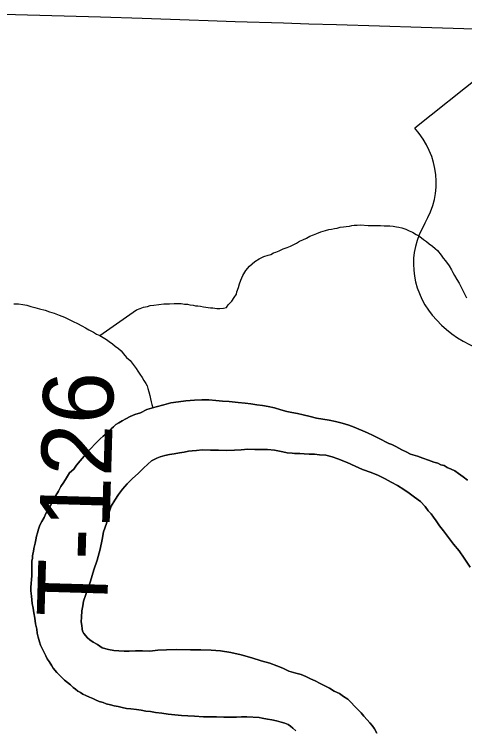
# Model space of a CAD drawing. Extents: x 2.1 to 73.9, y 4 to 26.
# Drawn here: x 43.881 to 44.0631, y 22.0785 to 22.368 of the extents above; entities that cross this region are included whole.
import ezdxf

# ---------------------------------------------------------------- set-up
doc = ezdxf.new("R2010")
doc.units = 0
for name, color, linetype in [('GM_X_County_Road', 7, 'Continuous'), ('GM_X_Major_River', 7, 'Continuous'), ('GM_X_Minor_River', 7, 'Continuous'), ('GM_X_Township_Road_Text', 7, 'Continuous'), ('GM_X_US_Shield', 7, 'Continuous')]:
    doc.layers.add(name, color=color, linetype=linetype)

msp = doc.modelspace()

# ---------------------------------------------------------------- linework, layer by layer
at = {"layer": 'GM_X_County_Road'}
msp.add_lwpolyline([(43.87654, 22.368), (43.89134, 22.36761), (43.91589, 22.36695), (43.93267, 22.36645), (43.95162, 22.36577), (43.95938, 22.36552), (43.97026, 22.36514), (43.98982, 22.3645), (44.00007, 22.36416), (44.01125, 22.36384), (44.02865, 22.36335), (44.04542, 22.36273), (44.06698, 22.36211), (44.08797, 22.36138), (44.10382, 22.36093), (44.1234, 22.36019), (44.12722, 22.36005)], dxfattribs=at)
at = {"layer": 'GM_X_Major_River'}
for points in [[(44.02771, 22.19681), (44.02601, 22.1976), (44.02374, 22.19859), (44.01845, 22.20095), (44.01619, 22.20175), (44.01353, 22.20255), (44.01088, 22.20316), (44.00823, 22.20378), (44.00576, 22.2042), (44.00311, 22.20462), (44.00064, 22.20523), (43.9978, 22.20585), (43.99553, 22.20645), (43.99325, 22.20687), (43.99117, 22.20728), (43.98871, 22.20789), (43.98624, 22.2087), (43.98359, 22.20931), (43.98132, 22.20973), (43.97904, 22.20995), (43.97657, 22.21037), (43.97429, 22.2106), (43.97144, 22.21084), (43.96784, 22.21127), (43.96518, 22.21151), (43.96252, 22.21174), (43.95967, 22.21198), (43.95682, 22.21202), (43.95377, 22.21188), (43.95035, 22.21156), (43.9473, 22.21123), (43.94425, 22.21071), (43.94138, 22.20999), (43.93833, 22.20909), (43.9345, 22.20802), (43.93201, 22.20673), (43.92972, 22.206), (43.92781, 22.20528), (43.92608, 22.20435), (43.92454, 22.20343), (43.9232, 22.20269), (43.92205, 22.20195), (43.92108, 22.20102), (43.92012, 22.20027), (43.91915, 22.19934), (43.91819, 22.1984), (43.91684, 22.19728), (43.91568, 22.19616), (43.91452, 22.19504), (43.91336, 22.19392), (43.9122, 22.19261), (43.91104, 22.1913), (43.90988, 22.18999), (43.90619, 22.18549), (43.90503, 22.18399), (43.9033, 22.18249), (43.90212, 22.18042), (43.90095, 22.17873), (43.89978, 22.17685), (43.8988, 22.17497), (43.89783, 22.17327), (43.89704, 22.17176), (43.89626, 22.17045), (43.89548, 22.16894), (43.8945, 22.16744), (43.89372, 22.16593), (43.89312, 22.16442), (43.89214, 22.16272), (43.89136, 22.16122), (43.89077, 22.15971), (43.89036, 22.15819), (43.88996, 22.15687), (43.88975, 22.15535), (43.88935, 22.15403), (43.88914, 22.15289), (43.88893, 22.15176), (43.88872, 22.15062), (43.88852, 22.14967), (43.88831, 22.14873), (43.8883, 22.14778), (43.88809, 22.14683), (43.88808, 22.14588), (43.88806, 22.14493), (43.88804, 22.14379), (43.88802, 22.14227), (43.888, 22.14075), (43.88797, 22.13923), (43.88776, 22.13771), (43.88773, 22.1362), (43.88771, 22.13468), (43.88787, 22.13258), (43.88803, 22.13106), (43.8882, 22.12954), (43.88855, 22.12763), (43.8889, 22.12573), (43.88925, 22.12363), (43.88959, 22.12134), (43.89013, 22.11925), (43.89029, 22.11753), (43.89065, 22.11601), (43.89119, 22.1141)], [(43.89119, 22.1141), (43.89065, 22.11601), (43.89029, 22.11753), (43.89013, 22.11925), (43.88959, 22.12134), (43.88925, 22.12363), (43.8889, 22.12573), (43.88855, 22.12763), (43.8882, 22.12954), (43.88803, 22.13106), (43.88787, 22.13258), (43.88771, 22.13468), (43.88773, 22.1362), (43.88776, 22.13771), (43.88797, 22.13923), (43.888, 22.14075), (43.88802, 22.14227), (43.88804, 22.14379), (43.88806, 22.14493), (43.88808, 22.14588), (43.88809, 22.14683), (43.8883, 22.14778), (43.88831, 22.14873), (43.88852, 22.14967), (43.88872, 22.15062), (43.88893, 22.15176), (43.88914, 22.15289), (43.88935, 22.15403), (43.88975, 22.15535), (43.88996, 22.15687), (43.89036, 22.15819), (43.89077, 22.15971), (43.89136, 22.16122), (43.89214, 22.16272), (43.89312, 22.16442), (43.89372, 22.16593), (43.8945, 22.16744), (43.89548, 22.16894), (43.89626, 22.17045), (43.89704, 22.17176), (43.89783, 22.17327), (43.8988, 22.17497), (43.89978, 22.17685), (43.90095, 22.17873), (43.90212, 22.18042), (43.9033, 22.18249), (43.90503, 22.18399), (43.90619, 22.18549), (43.90988, 22.18999), (43.91104, 22.1913), (43.9122, 22.19261), (43.91336, 22.19392), (43.91452, 22.19504), (43.91568, 22.19616), (43.91684, 22.19728), (43.91819, 22.1984), (43.91915, 22.19934), (43.92012, 22.20027), (43.92108, 22.20102), (43.92205, 22.20195), (43.9232, 22.20269), (43.92454, 22.20343), (43.92608, 22.20435), (43.92781, 22.20528), (43.92972, 22.206), (43.93201, 22.20673), (43.9345, 22.20802), (43.93833, 22.20909), (43.94138, 22.20999), (43.94425, 22.21071), (43.9473, 22.21123), (43.95035, 22.21156), (43.95377, 22.21188), (43.95682, 22.21202), (43.95967, 22.21198), (43.96252, 22.21174), (43.96518, 22.21151), (43.96784, 22.21127), (43.97144, 22.21084), (43.97429, 22.2106), (43.97657, 22.21037), (43.97904, 22.20995), (43.98132, 22.20973), (43.98359, 22.20931), (43.98624, 22.2087), (43.98871, 22.20789), (43.99117, 22.20728), (43.99325, 22.20687), (43.99553, 22.20645), (43.9978, 22.20585), (44.00064, 22.20523), (44.00311, 22.20462), (44.00576, 22.2042), (44.00823, 22.20378), (44.01088, 22.20316), (44.01353, 22.20255), (44.01619, 22.20175), (44.01845, 22.20095), (44.02374, 22.19859), (44.02601, 22.1976), (44.02771, 22.19681)], [(44.06414, 22.1795), (44.06245, 22.18086), (44.06057, 22.18222), (44.05907, 22.18319), (44.05756, 22.18398), (44.05604, 22.18457), (44.05472, 22.18535), (44.0534, 22.18575), (44.05227, 22.18634), (44.05056, 22.18675), (44.04848, 22.18754), (44.04621, 22.18834), (44.04394, 22.18914), (44.0411, 22.18995), (44.03941, 22.19092), (44.03771, 22.19171), (44.03526, 22.19308), (44.03356, 22.19387), (44.03242, 22.19427), (44.0311, 22.19505), (44.02959, 22.19583), (44.02771, 22.19681)], [(44.02771, 22.19681), (44.02959, 22.19583), (44.0311, 22.19505), (44.03242, 22.19427), (44.03356, 22.19387), (44.03526, 22.19308), (44.03771, 22.19171), (44.03941, 22.19092), (44.0411, 22.18995), (44.04394, 22.18914), (44.04621, 22.18834), (44.04848, 22.18754), (44.05056, 22.18675), (44.05227, 22.18634), (44.0534, 22.18575), (44.05472, 22.18535), (44.05604, 22.18457), (44.05756, 22.18398), (44.05907, 22.18319), (44.06057, 22.18222), (44.06245, 22.18086), (44.06414, 22.1795)], [(44.02754, 22.07711), (44.02662, 22.07883), (44.02569, 22.08018), (44.02476, 22.08133), (44.02363, 22.08249), (44.02233, 22.08403), (44.02121, 22.08538), (44.0199, 22.08673), (44.01578, 22.09079), (44.01408, 22.09196), (44.01239, 22.09312), (44.01031, 22.09411), (44.00843, 22.09528), (44.00654, 22.09626), (44.00466, 22.09724), (44.00258, 22.09822), (44.00069, 22.09902), (43.9988, 22.1), (43.99691, 22.10079), (43.99483, 22.10139), (43.99199, 22.1022), (43.98954, 22.10338), (43.98708, 22.10437), (43.98424, 22.10536), (43.98084, 22.10637), (43.97705, 22.10757), (43.9727, 22.10878), (43.96853, 22.1098), (43.96435, 22.11044), (43.96055, 22.11069), (43.95637, 22.11076), (43.95219, 22.11082), (43.94648, 22.11092), (43.94249, 22.11079), (43.93906, 22.11066), (43.93582, 22.11033), (43.93278, 22.11038), (43.92993, 22.11043), (43.92746, 22.11028), (43.92537, 22.11031), (43.92327, 22.11035), (43.92118, 22.11057), (43.9191, 22.11098), (43.91645, 22.1116), (43.91457, 22.11296), (43.91287, 22.11393), (43.91155, 22.11491), (43.91061, 22.11568), (43.90912, 22.11742), (43.90857, 22.11837), (43.90839, 22.11933), (43.90822, 22.12066), (43.90805, 22.12218), (43.90808, 22.12408), (43.90831, 22.12655), (43.90873, 22.12863), (43.90895, 22.13053), (43.91174, 22.13865), (43.91314, 22.14319), (43.91453, 22.14716), (43.91574, 22.15151), (43.91656, 22.15549), (43.91699, 22.15852), (43.91819, 22.16192), (43.9192, 22.16608), (43.9202, 22.16892), (43.92157, 22.17137), (43.92312, 22.17362), (43.92468, 22.17587), (43.92662, 22.17793), (43.92874, 22.18018), (43.93106, 22.18223), (43.93318, 22.18429), (43.93492, 22.18597), (43.93646, 22.18727), (43.93857, 22.18838), (43.93991, 22.18893), (43.94182, 22.18947), (43.94373, 22.18982), (43.94564, 22.19016), (43.94773, 22.19051), (43.94964, 22.19086), (43.95136, 22.19121), (43.95288, 22.19138), (43.9546, 22.19154), (43.95688, 22.19169), (43.9603, 22.19164), (43.96353, 22.19158), (43.96696, 22.19153), (43.97, 22.19167), (43.97267, 22.19182), (43.97533, 22.19196), (43.97818, 22.19191)], [(43.97818, 22.19191), (43.97533, 22.19196), (43.97267, 22.19182), (43.97, 22.19167), (43.96696, 22.19153), (43.96353, 22.19158), (43.9603, 22.19164), (43.95688, 22.19169), (43.9546, 22.19154), (43.95288, 22.19138), (43.95136, 22.19121), (43.94964, 22.19086), (43.94773, 22.19051), (43.94564, 22.19016), (43.94373, 22.18982), (43.94182, 22.18947), (43.93991, 22.18893), (43.93857, 22.18838), (43.93646, 22.18727), (43.93492, 22.18597), (43.93318, 22.18429), (43.93106, 22.18223), (43.92874, 22.18018), (43.92662, 22.17793), (43.92468, 22.17587), (43.92312, 22.17362), (43.92157, 22.17137), (43.9202, 22.16892), (43.9192, 22.16608), (43.91819, 22.16192), (43.91699, 22.15852), (43.91656, 22.15549), (43.91574, 22.15151), (43.91453, 22.14716), (43.91314, 22.14319), (43.91174, 22.13865), (43.90895, 22.13053), (43.90873, 22.12863), (43.90831, 22.12655), (43.90808, 22.12408), (43.90805, 22.12218), (43.90822, 22.12066), (43.90839, 22.11933), (43.90857, 22.11837), (43.90912, 22.11742), (43.91061, 22.11568), (43.91155, 22.11491), (43.91287, 22.11393), (43.91457, 22.11296), (43.91645, 22.1116), (43.9191, 22.11098), (43.92118, 22.11057), (43.92327, 22.11035), (43.92537, 22.11031), (43.92746, 22.11028), (43.92993, 22.11043), (43.93278, 22.11038), (43.93582, 22.11033), (43.93906, 22.11066), (43.94249, 22.11079), (43.94648, 22.11092), (43.95219, 22.11082), (43.95637, 22.11076), (43.96055, 22.11069), (43.96435, 22.11044), (43.96853, 22.1098), (43.9727, 22.10878), (43.97705, 22.10757), (43.98084, 22.10637), (43.98424, 22.10536), (43.98708, 22.10437), (43.98954, 22.10338), (43.99199, 22.1022), (43.99483, 22.10139), (43.99691, 22.10079), (43.9988, 22.1), (44.00069, 22.09902), (44.00258, 22.09822), (44.00466, 22.09724), (44.00654, 22.09626), (44.00843, 22.09528), (44.01031, 22.09411), (44.01239, 22.09312), (44.01408, 22.09196), (44.01578, 22.09079), (44.0199, 22.08673), (44.02121, 22.08538), (44.02233, 22.08403), (44.02363, 22.08249), (44.02476, 22.08133), (44.02569, 22.08018), (44.02662, 22.07883), (44.02754, 22.07711)], [(43.97818, 22.19191), (43.98085, 22.19187), (43.98332, 22.19183), (43.98617, 22.1916), (43.98958, 22.19097), (43.99129, 22.19056), (43.99337, 22.19034), (43.99432, 22.19032), (43.99528, 22.19031), (43.99642, 22.19029), (43.99812, 22.19007), (44.00022, 22.19004), (44.00231, 22.19), (44.0044, 22.18978), (44.00687, 22.18955), (44.00952, 22.18894), (44.01179, 22.18814), (44.01557, 22.18656), (44.01878, 22.18518), (44.0218, 22.1838), (44.0252, 22.1826), (44.02823, 22.18141), (44.03087, 22.18004), (44.03332, 22.17867), (44.03596, 22.1773), (44.03841, 22.17574), (44.04067, 22.17418), (44.04273, 22.17263), (44.04518, 22.17088), (44.04705, 22.16876), (44.04835, 22.16703), (44.04947, 22.16587), (44.0504, 22.16452), (44.05152, 22.16298), (44.05282, 22.16106), (44.0545, 22.15895), (44.05655, 22.15625), (44.0586, 22.15356), (44.06084, 22.15086), (44.06289, 22.14798), (44.0653, 22.14433)], [(44.0653, 22.14433), (44.06289, 22.14798), (44.06084, 22.15086), (44.0586, 22.15356), (44.05655, 22.15625), (44.0545, 22.15895), (44.05282, 22.16106), (44.05152, 22.16298), (44.0504, 22.16452), (44.04947, 22.16587), (44.04835, 22.16703), (44.04705, 22.16876), (44.04518, 22.17088), (44.04273, 22.17263), (44.04067, 22.17418), (44.03841, 22.17574), (44.03596, 22.1773), (44.03332, 22.17867), (44.03087, 22.18004), (44.02823, 22.18141), (44.0252, 22.1826), (44.0218, 22.1838), (44.01878, 22.18518), (44.01557, 22.18656), (44.01179, 22.18814), (44.00952, 22.18894), (44.00687, 22.18955), (44.0044, 22.18978), (44.00231, 22.19), (44.00022, 22.19004), (43.99812, 22.19007), (43.99642, 22.19029), (43.99528, 22.19031), (43.99432, 22.19032), (43.99337, 22.19034), (43.99129, 22.19056), (43.98958, 22.19097), (43.98617, 22.1916), (43.98332, 22.19183), (43.98085, 22.19187), (43.97818, 22.19191)], [(43.89119, 22.1141), (43.89155, 22.11276), (43.89376, 22.10836), (43.89432, 22.10721), (43.89506, 22.10605), (43.89617, 22.10433), (43.89673, 22.10337), (43.89822, 22.10163), (43.89935, 22.10047), (43.90028, 22.09951), (43.90122, 22.09854), (43.90253, 22.09757), (43.90366, 22.0966), (43.90478, 22.09564), (43.90572, 22.09486), (43.90666, 22.09408), (43.90779, 22.0935), (43.90874, 22.09291), (43.90987, 22.09232), (43.91138, 22.09173), (43.9127, 22.09114), (43.91383, 22.09055), (43.91535, 22.08995), (43.91686, 22.08955), (43.91818, 22.08896), (43.91989, 22.08855), (43.9214, 22.08814), (43.92292, 22.08793), (43.92463, 22.08752), (43.92633, 22.08711), (43.92804, 22.0869), (43.93032, 22.08667), (43.93222, 22.08645), (43.93411, 22.08604), (43.93601, 22.08582), (43.9381, 22.0854), (43.94057, 22.08517), (43.94322, 22.08475), (43.94588, 22.08452), (43.94854, 22.08428), (43.9512, 22.08405), (43.95386, 22.08401), (43.95747, 22.08376), (43.96013, 22.08371), (43.96279, 22.08367), (43.96565, 22.08362), (43.96831, 22.08358), (43.97078, 22.08354), (43.97287, 22.0837), (43.97496, 22.08366), (43.97991, 22.08339), (43.98123, 22.08318), (43.98332, 22.08277), (43.98503, 22.08255), (43.98692, 22.08214), (43.98882, 22.08154), (43.99033, 22.08113), (43.99165, 22.08054), (43.99259, 22.07996), (43.99353, 22.07918), (43.99485, 22.07802)], [(43.99485, 22.07802), (43.99353, 22.07918), (43.99259, 22.07996), (43.99165, 22.08054), (43.99033, 22.08113), (43.98882, 22.08154), (43.98692, 22.08214), (43.98503, 22.08255), (43.98332, 22.08277), (43.98123, 22.08318), (43.97991, 22.08339), (43.97496, 22.08366), (43.97287, 22.0837), (43.97078, 22.08354), (43.96831, 22.08358), (43.96565, 22.08362), (43.96279, 22.08367), (43.96013, 22.08371), (43.95747, 22.08376), (43.95386, 22.08401), (43.9512, 22.08405), (43.94854, 22.08428), (43.94588, 22.08452), (43.94322, 22.08475), (43.94057, 22.08517), (43.9381, 22.0854), (43.93601, 22.08582), (43.93411, 22.08604), (43.93222, 22.08645), (43.93032, 22.08667), (43.92804, 22.0869), (43.92633, 22.08711), (43.92463, 22.08752), (43.92292, 22.08793), (43.9214, 22.08814), (43.91989, 22.08855), (43.91818, 22.08896), (43.91686, 22.08955), (43.91535, 22.08995), (43.91383, 22.09055), (43.9127, 22.09114), (43.91138, 22.09173), (43.90987, 22.09232), (43.90874, 22.09291), (43.90779, 22.0935), (43.90666, 22.09408), (43.90572, 22.09486), (43.90478, 22.09564), (43.90366, 22.0966), (43.90253, 22.09757), (43.90122, 22.09854), (43.90028, 22.09951), (43.89935, 22.10047), (43.89822, 22.10163), (43.89673, 22.10337), (43.89617, 22.10433), (43.89506, 22.10605), (43.89432, 22.10721), (43.89376, 22.10836), (43.89155, 22.11276), (43.89119, 22.1141)]]:
    msp.add_lwpolyline(points, dxfattribs=at)
at = {"layer": 'GM_X_Minor_River'}
for points in [[(43.91558, 22.23796), (43.93038, 22.24836), (43.93191, 22.24891), (43.93325, 22.24946), (43.93478, 22.24981), (43.93593, 22.25018), (43.93745, 22.25034), (43.93935, 22.2505), (43.94145, 22.25085), (43.94373, 22.25081), (43.94564, 22.25097), (43.94716, 22.25094), (43.94849, 22.25092), (43.94982, 22.25071), (43.95096, 22.25069), (43.95191, 22.25048), (43.95324, 22.25027), (43.95418, 22.25007), (43.95513, 22.25005), (43.95627, 22.24984), (43.95741, 22.24964), (43.95836, 22.24943), (43.95931, 22.24941), (43.96026, 22.24921), (43.96121, 22.24919), (43.96291, 22.24898), (43.96406, 22.24896), (43.96558, 22.24912), (43.96672, 22.24929), (43.9675, 22.25042), (43.96886, 22.25192), (43.96983, 22.25342), (43.9708, 22.25474), (43.97101, 22.25568), (43.9716, 22.25739), (43.97201, 22.2589), (43.9726, 22.26041), (43.973, 22.26135), (43.97339, 22.2623), (43.97457, 22.26437), (43.97612, 22.26605), (43.97708, 22.26699), (43.97824, 22.26792), (43.97996, 22.26903), (43.98188, 22.26995), (43.9836, 22.27049), (43.98475, 22.27085), (43.98571, 22.27141), (43.98666, 22.27177), (43.988, 22.27232), (43.98973, 22.27305), (43.99126, 22.2736), (43.9926, 22.27415), (43.99394, 22.27488), (43.99509, 22.27543), (43.99624, 22.27618), (43.99758, 22.27673), (43.99912, 22.27746), (44.00046, 22.2782), (44.00199, 22.27874), (44.00333, 22.27929), (44.00486, 22.28003), (44.00677, 22.28057), (44.00811, 22.28092), (44.00925, 22.2811), (44.0104, 22.28127), (44.01154, 22.28144), (44.01269, 22.2818), (44.01402, 22.28197), (44.01516, 22.28214), (44.0165, 22.28231), (44.01745, 22.28248), (44.01841, 22.28266), (44.01955, 22.28264), (44.02088, 22.28281), (44.02411, 22.28257), (44.02506, 22.28255), (44.02601, 22.28253), (44.02715, 22.28252), (44.0281, 22.2825), (44.02905, 22.28248), (44.03057, 22.28246), (44.03153, 22.28244), (44.03285, 22.28242), (44.03418, 22.28221), (44.03551, 22.282), (44.03646, 22.2818), (44.0376, 22.28159), (44.0393, 22.28099), (44.04062, 22.2804), (44.04194, 22.27981), (44.04345, 22.27883), (44.04496, 22.27805), (44.04646, 22.27688), (44.04759, 22.2761), (44.04872, 22.27514), (44.05003, 22.27416)], [(44.05003, 22.27416), (44.05116, 22.2732), (44.0521, 22.27242), (44.05359, 22.2705), (44.05433, 22.26934), (44.05526, 22.26819), (44.05676, 22.26627), (44.05768, 22.26454), (44.05823, 22.26358), (44.05897, 22.26224), (44.0599, 22.2607), (44.06083, 22.25917), (44.06157, 22.25783), (44.06378, 22.25323)], [(43.88079, 22.25088), (43.88269, 22.25085), (43.88439, 22.25063), (43.8861, 22.25023), (43.88762, 22.24982), (43.88932, 22.24941), (43.89121, 22.24881), (43.89349, 22.24821), (43.89519, 22.24761), (43.89708, 22.24701), (43.89916, 22.24621), (43.90124, 22.24542), (43.90294, 22.24463), (43.90482, 22.24365), (43.90652, 22.24286), (43.90822, 22.24189), (43.90973, 22.2411), (43.91105, 22.24032), (43.91294, 22.23934), (43.91425, 22.23856), (43.91558, 22.23796), (43.91689, 22.23718), (43.91821, 22.2364), (43.91934, 22.23562), (43.92066, 22.23465), (43.92178, 22.23368), (43.9231, 22.23271), (43.92423, 22.23175), (43.92516, 22.23059), (43.92628, 22.22905)], [(43.92628, 22.22905), (43.92778, 22.22789), (43.9302, 22.22462), (43.93095, 22.22365), (43.93169, 22.22231), (43.93262, 22.22097), (43.93336, 22.21982), (43.9341, 22.21866), (43.93466, 22.2177), (43.93502, 22.21656), (43.93538, 22.21522), (43.93573, 22.2137), (43.93609, 22.21236), (43.93627, 22.21122), (43.93663, 22.21007), (43.93701, 22.20877)]]:
    msp.add_lwpolyline(points, dxfattribs=at)
at = {"layer": 'GM_X_US_Shield'}
msp.add_line((44.07723, 22.34939), (44.04289, 22.32192), dxfattribs=at)
for centre, start_param, end_param in [((44.00352, 22.29987), 5.838949, 6.894067), ((44.09042, 22.26699), 2.702327, 4.723529)]:
    msp.add_ellipse(centre, major_axis=(0.04807, 0), ratio=0.8, start_param=start_param, end_param=end_param, dxfattribs=at)

# ---------------------------------------------------------------- texts
at = {"layer": 'GM_X_Township_Road_Text'}
msp.add_text('T-126', height=0.028409, rotation=88.3318, dxfattribs=at).set_placement((43.91843, 22.12375))

doc.saveas('drawing.dxf')
